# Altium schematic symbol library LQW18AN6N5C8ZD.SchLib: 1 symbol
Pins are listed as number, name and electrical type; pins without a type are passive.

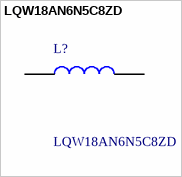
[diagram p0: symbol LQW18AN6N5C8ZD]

## LQW18AN6N5C8ZD
designator L?
LQW18AN_8Z Series Inductor 6.5nH +/-0.2nH 0603 (1608); Manufacturer_Name: Murata Electronics; Geometry.Height: 1mm
footprint LQW18AN10NG80D
pins: 1, 2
